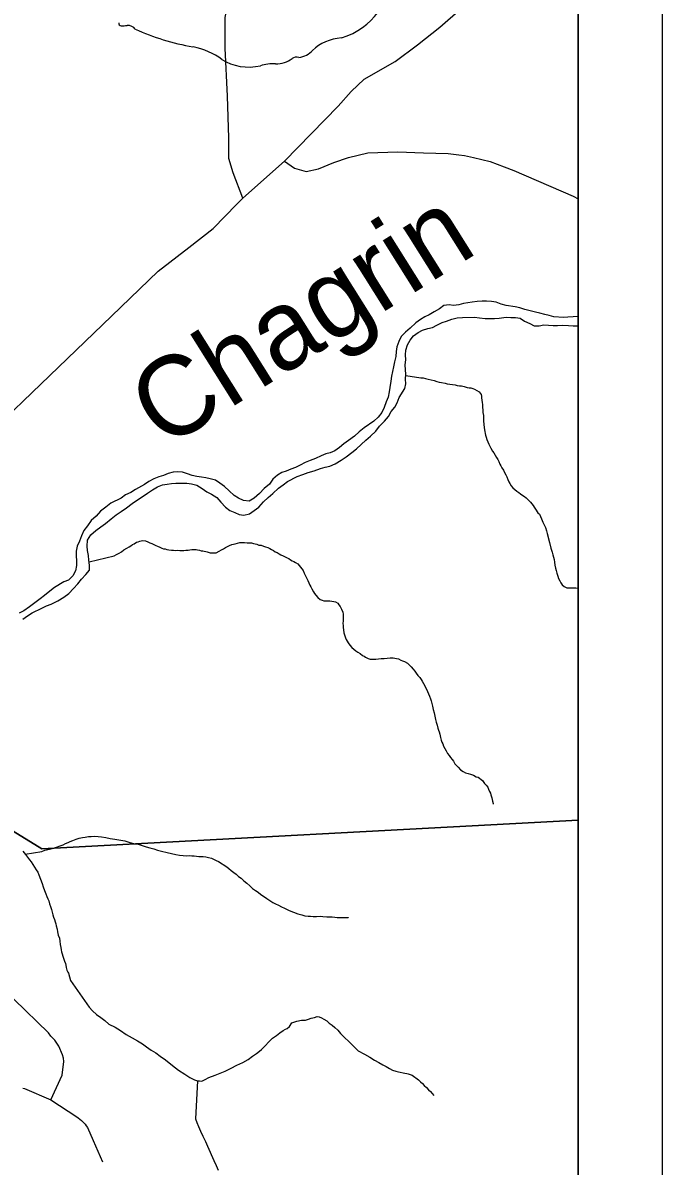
# Model space of a CAD drawing. Extents: x 0 to 44.3, y 0 to 22.
# Drawn here: x 8.24 to 9, y 17.041 to 18.401 of the extents above; entities that cross this region are included whole.
import ezdxf

# ---------------------------------------------------------------- set-up
doc = ezdxf.new("R2010")
doc.units = 0
for name, color, linetype in [('GM_X_City_Street', 7, 'Continuous'), ('GM_X_Corporation', 7, 'Continuous'), ('GM_X_County_Road', 7, 'Continuous'), ('GM_X_Minor_River', 7, 'Continuous'), ('GM_X_Minor_River_Text', 7, 'Continuous'), ('GM_X_State_Route', 7, 'Continuous'), ('GM_X_State_Shield', 7, 'Continuous'), ('SH_Data', 7, 'Continuous')]:
    doc.layers.add(name, color=color, linetype=linetype)

msp = doc.modelspace()

# ---------------------------------------------------------------- linework, layer by layer
at = {"layer": 'GM_X_City_Street'}
for points in [[(8.5507, 18.2363), (8.5628, 18.2282), (8.5765, 18.2242), (8.5913, 18.2273), (8.6095, 18.2347), (8.6269, 18.2407), (8.6499, 18.2464), (8.6858, 18.2473), (8.7162, 18.2461), (8.7454, 18.2454), (8.7581, 18.2438), (8.7651, 18.243), (8.7756, 18.2407), (8.7955, 18.2358), (8.8122, 18.2296), (8.8237, 18.2251), (8.8942, 18.1946), (8.9, 18.1917)], [(8.2727, 17.1196), (8.2864, 17.1487), (8.2884, 17.165), (8.2879, 17.1689), (8.2866, 17.1731), (8.2824, 17.1832), (8.2775, 17.1905), (8.2729, 17.1954), (8.27, 17.1993), (8.2291, 17.239), (8.1807, 17.2908)], [(8.2394, 17.1336), (8.2414, 17.133), (8.2727, 17.1196), (8.3037, 17.0991), (8.3054, 17.098), (8.3075, 17.0965), (8.3094, 17.0949), (8.3136, 17.0904), (8.3151, 17.0884), (8.3166, 17.0865), (8.3233, 17.0713), (8.3342, 17.0458)]]:
    msp.add_lwpolyline(points, dxfattribs=at)
at = {"layer": 'GM_X_Corporation'}
for points in [[(8.9, 14.1), (8.9, 20.9), (3.6041, 20.9)], [(8.9, 14.1), (8.9, 20.9), (3.6041, 20.9)], [(8.0905, 17.5236), (8.262, 17.4181), (8.9, 17.4522), (8.9, 19.3141)], [(8.9, 14.1), (8.9, 17.4522), (8.262, 17.4181), (8.0905, 17.5236)]]:
    msp.add_lwpolyline(points, dxfattribs=at)
at = {"layer": 'GM_X_County_Road'}
msp.add_lwpolyline([(8.5014, 18.1922), (8.5507, 18.2363), (8.6148, 18.3016), (8.6301, 18.3193), (8.6454, 18.3338), (8.6823, 18.3548), (8.7091, 18.3746), (8.7357, 18.3959), (8.7607, 18.4177), (8.9, 18.5298)], dxfattribs=at)
at = {"layer": 'GM_X_Minor_River'}
for points in [[(8.9, 18.0516), (8.8994, 18.0516), (8.8941, 18.0512), (8.888, 18.0508), (8.8827, 18.0504), (8.8713, 18.0512), (8.8656, 18.0527), (8.8603, 18.0538), (8.8546, 18.0553), (8.8493, 18.0568), (8.8429, 18.0583), (8.8368, 18.0598), (8.8307, 18.0617), (8.825, 18.0632), (8.8144, 18.0647), (8.8087, 18.0662), (8.8026, 18.0685), (8.7969, 18.0692), (8.7912, 18.0696), (8.7859, 18.0699), (8.7799, 18.0695), (8.7742, 18.0684), (8.7636, 18.0669), (8.7583, 18.0653), (8.7518, 18.0645), (8.7465, 18.0653), (8.7404, 18.0645), (8.7351, 18.0607), (8.7287, 18.0569), (8.723, 18.0535), (8.7177, 18.0512), (8.7124, 18.0481), (8.7071, 18.0439), (8.7003, 18.0378), (8.6946, 18.0329), (8.6897, 18.0276), (8.6867, 18.0219), (8.6844, 18.0154), (8.6837, 18.0097), (8.6833, 18.004), (8.6815, 17.9975), (8.6803, 17.9915), (8.6792, 17.9862), (8.6781, 17.9805), (8.6774, 17.9744), (8.6762, 17.9672), (8.6755, 17.9618), (8.674, 17.9554), (8.6717, 17.9501), (8.6695, 17.9432), (8.6665, 17.9375), (8.6623, 17.9318), (8.657, 17.9269), (8.6457, 17.9192), (8.6396, 17.9143), (8.6339, 17.9093), (8.6271, 17.904), (8.6214, 17.9002), (8.6161, 17.8956), (8.6105, 17.8918), (8.6052, 17.8895), (8.5999, 17.888), (8.5946, 17.8857), (8.5877, 17.8827), (8.5813, 17.88), (8.5756, 17.8777), (8.5696, 17.8746), (8.5639, 17.872), (8.5582, 17.8697), (8.5529, 17.8674), (8.5476, 17.8659), (8.5423, 17.8628), (8.537, 17.8579), (8.5328, 17.8521), (8.5268, 17.8468), (8.5211, 17.8411), (8.5147, 17.8354), (8.5086, 17.832), (8.5022, 17.8327), (8.4961, 17.8354), (8.4908, 17.8384), (8.4851, 17.8441), (8.4794, 17.8494)], [(8.6951, 17.9999), (8.6947, 18.0059), (8.6951, 18.0116), (8.6973, 18.0177), (8.7004, 18.0234), (8.7041, 18.0287), (8.7098, 18.0325), (8.7151, 18.0352), (8.7212, 18.0371), (8.7269, 18.0383), (8.7322, 18.0413), (8.7382, 18.0444), (8.7435, 18.0459), (8.75, 18.0482), (8.7564, 18.0501), (8.7625, 18.0505), (8.7769, 18.0506), (8.7826, 18.0498), (8.7894, 18.0491), (8.8008, 18.0491), (8.8061, 18.0495), (8.8144, 18.0506), (8.8201, 18.0503), (8.8254, 18.0503), (8.8311, 18.0495), (8.8364, 18.0461), (8.8425, 18.0431), (8.8478, 18.0405), (8.8539, 18.0405), (8.8592, 18.0416), (8.8649, 18.0413), (8.8702, 18.0409), (8.8755, 18.0409), (8.8816, 18.0413), (8.8888, 18.0409), (8.8941, 18.0406), (8.9, 18.0406)], [(8.2394, 17.6916), (8.245, 17.6954), (8.2507, 17.6988), (8.2621, 17.7046), (8.2678, 17.7072), (8.2731, 17.7091), (8.2814, 17.7133), (8.2882, 17.7175), (8.2943, 17.7221), (8.2999, 17.7278), (8.3049, 17.7335), (8.3094, 17.7392), (8.3147, 17.7445), (8.3188, 17.7499), (8.3188, 17.7556), (8.318, 17.7616), (8.3177, 17.7673), (8.3165, 17.773), (8.3161, 17.7783), (8.3165, 17.7856), (8.3206, 17.7916), (8.3263, 17.797), (8.3323, 17.8012), (8.338, 17.8054), (8.3445, 17.8107), (8.3505, 17.8156), (8.3566, 17.8195), (8.363, 17.824), (8.3698, 17.829), (8.3759, 17.8335), (8.3827, 17.8377), (8.388, 17.8415), (8.3937, 17.8454), (8.3997, 17.8488), (8.4058, 17.8511), (8.4111, 17.8522), (8.4164, 17.853), (8.4217, 17.8534), (8.4278, 17.8534), (8.4346, 17.8531), (8.4403, 17.8523), (8.4467, 17.8508), (8.4528, 17.847), (8.4585, 17.8429), (8.4638, 17.8402), (8.4703, 17.8361), (8.4752, 17.8307), (8.4806, 17.8247), (8.4859, 17.8209), (8.4916, 17.8183), (8.4969, 17.816), (8.5026, 17.8152), (8.509, 17.8168), (8.5147, 17.8206), (8.5204, 17.8248), (8.5257, 17.8309), (8.5314, 17.8362), (8.537, 17.8411), (8.5438, 17.8472), (8.5491, 17.8514), (8.5544, 17.8552), (8.5658, 17.861), (8.5726, 17.8636), (8.5791, 17.8659), (8.5863, 17.8678), (8.5938, 17.8705), (8.5991, 17.8724), (8.6048, 17.8736), (8.6109, 17.8763), (8.6181, 17.8804), (8.6241, 17.8846), (8.6309, 17.8896), (8.6366, 17.8942), (8.6419, 17.8991), (8.6476, 17.9044), (8.6533, 17.909), (8.6593, 17.9151), (8.6639, 17.9212), (8.6699, 17.9269), (8.6744, 17.9326), (8.6778, 17.9383), (8.682, 17.9436), (8.685, 17.949), (8.6873, 17.955), (8.6941, 17.9657), (8.6952, 17.9714), (8.6948, 17.9771), (8.6952, 17.9828), (8.6948, 17.9881), (8.6944, 17.9942), (8.6951, 17.9999)], [(8.6951, 17.9812), (8.7131, 17.9787), (8.7158, 17.9784), (8.7185, 17.9777), (8.7219, 17.977), (8.7254, 17.976), (8.7288, 17.9753), (8.7319, 17.9742), (8.7346, 17.9735), (8.7376, 17.9729), (8.7418, 17.9722), (8.7445, 17.9715), (8.7476, 17.9712), (8.7507, 17.9705), (8.7537, 17.9702), (8.7564, 17.9695), (8.7591, 17.9692), (8.7614, 17.9689), (8.7644, 17.9682), (8.7679, 17.9672), (8.7706, 17.9668), (8.7725, 17.9665), (8.7748, 17.9658), (8.7767, 17.9651), (8.7794, 17.9636), (8.7825, 17.9618), (8.7849, 17.9588), (8.7853, 17.9569), (8.7853, 17.9547), (8.7854, 17.952), (8.7859, 17.9493), (8.7863, 17.9467), (8.7864, 17.9436), (8.7869, 17.9402), (8.7869, 17.9372), (8.7874, 17.9338), (8.7875, 17.9303), (8.7876, 17.9273), (8.7881, 17.9231), (8.7882, 17.9193), (8.7886, 17.9167), (8.7899, 17.9102), (8.7907, 17.908), (8.7916, 17.9053), (8.7928, 17.9023), (8.794, 17.8997), (8.7952, 17.8974), (8.7964, 17.8948), (8.7984, 17.8914), (8.8, 17.8892), (8.8016, 17.8865), (8.8028, 17.8839), (8.8044, 17.8813), (8.8056, 17.879), (8.8068, 17.876), (8.808, 17.8737), (8.8092, 17.8715), (8.8115, 17.8685), (8.8124, 17.8659), (8.814, 17.8632), (8.8152, 17.8606), (8.8164, 17.8576), (8.8176, 17.855), (8.8188, 17.8527), (8.8204, 17.8501), (8.8224, 17.8478), (8.8247, 17.8456), (8.827, 17.8438), (8.8294, 17.8423), (8.8317, 17.8405), (8.8344, 17.8386), (8.8363, 17.8372), (8.8383, 17.8357), (8.8402, 17.8338), (8.8434, 17.8305), (8.8449, 17.8286), (8.8465, 17.8267), (8.8477, 17.8245), (8.8493, 17.8223), (8.8521, 17.8181), (8.854, 17.8163), (8.8552, 17.8136), (8.8565, 17.8106), (8.8581, 17.8069), (8.8597, 17.8035), (8.8613, 17.8005), (8.8625, 17.7967), (8.8634, 17.7933), (8.8659, 17.7827), (8.8676, 17.7759), (8.8693, 17.771), (8.8701, 17.7679), (8.8709, 17.7653), (8.8714, 17.7623), (8.8719, 17.7592), (8.8723, 17.7558), (8.8732, 17.752), (8.874, 17.7494)], [(8.4794, 17.8494), (8.474, 17.8531), (8.4687, 17.8566), (8.4626, 17.8584), (8.4573, 17.8596), (8.452, 17.8603), (8.4467, 17.8611), (8.441, 17.8622), (8.4353, 17.8644), (8.4296, 17.8663), (8.4239, 17.8667), (8.4183, 17.8663), (8.4126, 17.8648), (8.4069, 17.8625), (8.4012, 17.8606), (8.3955, 17.8583), (8.3895, 17.8552), (8.3842, 17.8518), (8.3736, 17.8457), (8.3679, 17.8423), (8.3618, 17.8392), (8.3565, 17.8354), (8.3444, 17.8293), (8.3384, 17.8247), (8.3319, 17.8198), (8.327, 17.8141), (8.321, 17.8087), (8.3164, 17.8023), (8.3123, 17.7969), (8.3092, 17.7905), (8.307, 17.7844), (8.3043, 17.7783), (8.3029, 17.7722), (8.3029, 17.7669), (8.3036, 17.7608), (8.3033, 17.7552), (8.3022, 17.7491), (8.2991, 17.743), (8.2938, 17.738), (8.2885, 17.7358), (8.2772, 17.7289), (8.2715, 17.7247), (8.2655, 17.7194), (8.2602, 17.7156), (8.2537, 17.711), (8.2477, 17.706), (8.2409, 17.7015), (8.2352, 17.6984)], [(8.3183, 17.7596), (8.3483, 17.7669), (8.3509, 17.7684), (8.3543, 17.7701), (8.3569, 17.7716), (8.3599, 17.774), (8.3633, 17.776), (8.3659, 17.7776), (8.3681, 17.7788), (8.37, 17.7804), (8.3719, 17.7812), (8.3749, 17.7831), (8.3768, 17.7836), (8.3787, 17.7844), (8.3821, 17.7852), (8.3855, 17.7846), (8.3882, 17.7835), (8.3905, 17.7824), (8.3932, 17.7813), (8.3955, 17.7802), (8.3978, 17.7792), (8.3998, 17.7781), (8.4025, 17.777), (8.4048, 17.7759), (8.4067, 17.7752), (8.409, 17.7749), (8.4109, 17.7742), (8.4132, 17.7738), (8.4163, 17.7735), (8.4186, 17.7736), (8.4212, 17.7733), (8.4239, 17.7734), (8.4262, 17.773), (8.4289, 17.7731), (8.4311, 17.7732), (8.4334, 17.7736), (8.4361, 17.7737), (8.4384, 17.7741), (8.4406, 17.7742), (8.4433, 17.7742), (8.4456, 17.7743), (8.4475, 17.774), (8.4498, 17.7736), (8.4517, 17.7729), (8.4536, 17.7726), (8.459, 17.7716), (8.4624, 17.7705), (8.4644, 17.7702), (8.4666, 17.7703), (8.4697, 17.7703), (8.4731, 17.7723), (8.4757, 17.7739), (8.4783, 17.7751), (8.4806, 17.7767), (8.4832, 17.7779), (8.4855, 17.7791), (8.4881, 17.7803), (8.4923, 17.7812), (8.4949, 17.782), (8.4976, 17.7825), (8.5006, 17.7825), (8.5033, 17.7826), (8.5063, 17.7823), (8.509, 17.7824), (8.5117, 17.7821), (8.514, 17.7814), (8.5159, 17.781), (8.5178, 17.7807), (8.5201, 17.7796), (8.5232, 17.7793), (8.5259, 17.7782), (8.5282, 17.7775), (8.5309, 17.7765), (8.5332, 17.7754), (8.5355, 17.7743), (8.5378, 17.7732), (8.5397, 17.7717), (8.5421, 17.7706), (8.5444, 17.7692), (8.5463, 17.7681), (8.5494, 17.7666), (8.5517, 17.7656), (8.554, 17.7645), (8.556, 17.7634), (8.5579, 17.7619), (8.5598, 17.7608), (8.5618, 17.7601), (8.5641, 17.759), (8.5668, 17.7572), (8.5731, 17.7494), (8.5743, 17.7463), (8.5759, 17.7429), (8.5775, 17.7399), (8.5787, 17.7373), (8.5799, 17.7347), (8.5811, 17.732), (8.5823, 17.7298), (8.5835, 17.7275)], [(8.874, 17.7494), (8.8749, 17.746), (8.8761, 17.7426), (8.8769, 17.7399), (8.8782, 17.7369), (8.8794, 17.7347), (8.8809, 17.7321), (8.8833, 17.7302), (8.8867, 17.7288), (8.8894, 17.7285), (8.8928, 17.7285), (8.8955, 17.7286), (8.8974, 17.7287), (8.8997, 17.7283), (8.9, 17.7283)], [(8.5835, 17.7275), (8.5852, 17.7241), (8.5864, 17.7219), (8.5879, 17.72), (8.5903, 17.717), (8.5934, 17.7148), (8.5957, 17.7141), (8.5976, 17.7134), (8.5999, 17.7131), (8.6018, 17.7131), (8.6049, 17.7132), (8.6072, 17.7129), (8.6094, 17.7126), (8.6114, 17.7119), (8.6141, 17.7104), (8.6156, 17.7086), (8.6172, 17.7063), (8.6188, 17.7033), (8.6201, 17.6999), (8.6205, 17.6973), (8.6206, 17.6953), (8.6206, 17.6931), (8.6207, 17.6893), (8.6204, 17.6862), (8.6205, 17.6839), (8.6205, 17.6816), (8.621, 17.6786), (8.6215, 17.6752), (8.6235, 17.6692), (8.6243, 17.6673), (8.6267, 17.6631), (8.6287, 17.6605), (8.631, 17.6579), (8.6334, 17.6557), (8.6357, 17.6538), (8.638, 17.652), (8.6408, 17.6506), (8.6435, 17.6483), (8.6454, 17.6472), (8.6473, 17.6461), (8.6504, 17.6447), (8.6527, 17.644), (8.6554, 17.6437), (8.6573, 17.6437), (8.6596, 17.6438), (8.6626, 17.6443), (8.6657, 17.6447), (8.6695, 17.6448), (8.6729, 17.6449), (8.6767, 17.6454), (8.6801, 17.6455), (8.682, 17.6451), (8.6839, 17.6448), (8.6866, 17.6441), (8.6893, 17.6426), (8.6913, 17.6419), (8.6936, 17.6409), (8.697, 17.639), (8.6998, 17.6364), (8.7013, 17.6346), (8.7037, 17.632), (8.7057, 17.6297), (8.7076, 17.6271), (8.7096, 17.6245), (8.7116, 17.6219), (8.7132, 17.6196), (8.7144, 17.6178), (8.7163, 17.6148), (8.7196, 17.608), (8.7208, 17.6054), (8.722, 17.6024), (8.7232, 17.5997), (8.7244, 17.5967), (8.7252, 17.5941), (8.7261, 17.591), (8.7269, 17.588), (8.7278, 17.5838), (8.7287, 17.5801), (8.7295, 17.5759), (8.7304, 17.5721), (8.7312, 17.5687), (8.7325, 17.5653), (8.7333, 17.5619), (8.7341, 17.5593), (8.7349, 17.5574), (8.7354, 17.5547), (8.7358, 17.5528), (8.7363, 17.5506), (8.7371, 17.5475), (8.7379, 17.5449), (8.7391, 17.543), (8.74, 17.5404), (8.7416, 17.5374), (8.7431, 17.5347), (8.7447, 17.5317), (8.7467, 17.5291), (8.7483, 17.5269), (8.7503, 17.5243), (8.7518, 17.5224), (8.7534, 17.5194), (8.7554, 17.5175)], [(8.7554, 17.5175), (8.7574, 17.5153), (8.7601, 17.5123), (8.7632, 17.5101), (8.7663, 17.5087), (8.7694, 17.5076), (8.772, 17.5069), (8.7755, 17.5059), (8.779, 17.504), (8.7813, 17.5033), (8.7863, 17.4993), (8.7887, 17.4959), (8.7907, 17.4941), (8.7926, 17.4914), (8.7935, 17.4892), (8.7947, 17.4865), (8.7959, 17.4843), (8.7963, 17.4824), (8.7975, 17.479), (8.798, 17.4767), (8.7984, 17.4748), (8.7992, 17.4722), (8.7992, 17.4718), (8.7996, 17.4714)], [(8.2423, 17.412), (8.262, 17.4151), (8.2658, 17.4164), (8.2711, 17.4176), (8.276, 17.4189), (8.2874, 17.423), (8.2904, 17.4246), (8.2934, 17.4258), (8.296, 17.427), (8.299, 17.4282), (8.3032, 17.4295), (8.3066, 17.4307), (8.3104, 17.4316), (8.3138, 17.432), (8.3176, 17.4329), (8.321, 17.433), (8.3248, 17.4331), (8.329, 17.4328), (8.3332, 17.4325), (8.3382, 17.4315), (8.3435, 17.4305), (8.3489, 17.4295), (8.3562, 17.4286), (8.3608, 17.4275), (8.3657, 17.4261), (8.3711, 17.4247), (8.3769, 17.4237), (8.3815, 17.4223), (8.3861, 17.4206), (8.3907, 17.4195), (8.3953, 17.4181), (8.3999, 17.4167), (8.4045, 17.4153), (8.4114, 17.4136), (8.4164, 17.4126), (8.4214, 17.4116), (8.426, 17.4105), (8.4301, 17.4103), (8.4343, 17.41), (8.4374, 17.4101), (8.4404, 17.4098), (8.4435, 17.4098), (8.4462, 17.4095), (8.4488, 17.4092), (8.4511, 17.4089), (8.4542, 17.409), (8.4572, 17.4087), (8.4603, 17.408), (8.4641, 17.4069), (8.4664, 17.4058), (8.4695, 17.4044), (8.4722, 17.4029), (8.4823, 17.3967), (8.4846, 17.3949), (8.4874, 17.3923), (8.4905, 17.3901), (8.4932, 17.3879), (8.4963, 17.3853), (8.4994, 17.3831), (8.5025, 17.3801), (8.506, 17.3772), (8.5095, 17.3742), (8.5127, 17.3709), (8.5165, 17.3687), (8.5196, 17.3665), (8.5228, 17.3639), (8.5259, 17.3617), (8.5297, 17.3591), (8.5332, 17.3565), (8.5371, 17.3543), (8.5402, 17.3529), (8.5437, 17.3511), (8.5471, 17.3493), (8.551, 17.3475), (8.5564, 17.3449), (8.5614, 17.3428), (8.5668, 17.341), (8.5714, 17.3396), (8.5752, 17.3386), (8.579, 17.3379), (8.5817, 17.338), (8.5851, 17.3377), (8.589, 17.3378), (8.5931, 17.3379), (8.5966, 17.3376), (8.6012, 17.3373), (8.6046, 17.3374), (8.6076, 17.3371), (8.6107, 17.3368), (8.6134, 17.3365), (8.616, 17.3365), (8.6179, 17.3366), (8.6202, 17.3363), (8.6225, 17.3363), (8.6248, 17.3364), (8.6267, 17.3364), (8.6267, 17.3361), (8.6267, 17.3364)], [(8.2395, 17.4153), (8.2411, 17.4134), (8.2427, 17.4116), (8.2439, 17.4097), (8.2474, 17.4052), (8.2494, 17.4026)], [(8.2494, 17.4026), (8.2514, 17.3996), (8.2534, 17.3962), (8.2554, 17.3932), (8.2573, 17.3902), (8.2586, 17.3872), (8.2626, 17.3771), (8.2639, 17.3729), (8.2655, 17.3684), (8.2668, 17.3646), (8.268, 17.3616), (8.2692, 17.3586), (8.2704, 17.3563), (8.2712, 17.3529), (8.2725, 17.3495), (8.2737, 17.3461), (8.2745, 17.3427), (8.2754, 17.3397), (8.2762, 17.3367), (8.2771, 17.334), (8.2779, 17.3314), (8.2787, 17.3291), (8.2792, 17.3264), (8.2804, 17.3227), (8.2809, 17.3193), (8.2817, 17.3155), (8.283, 17.3117), (8.2834, 17.3083), (8.2839, 17.3045), (8.2848, 17.3007), (8.2852, 17.298), (8.2857, 17.2958), (8.2865, 17.2931), (8.2873, 17.2905), (8.2878, 17.2882), (8.289, 17.2844), (8.2902, 17.2818), (8.2906, 17.2799), (8.2911, 17.2769), (8.2919, 17.2738), (8.2931, 17.2716), (8.2939, 17.2701), (8.2964, 17.2616)], [(8.2964, 17.2616), (8.3184, 17.2298), (8.3226, 17.2253), (8.3273, 17.2212), (8.3323, 17.2175), (8.3373, 17.2141), (8.3419, 17.2097), (8.3496, 17.206), (8.3557, 17.2019), (8.3626, 17.1974), (8.3695, 17.1933), (8.376, 17.1896), (8.3818, 17.1863), (8.3868, 17.1826), (8.3922, 17.1788), (8.3976, 17.1755), (8.4029, 17.1714), (8.4091, 17.1673), (8.4176, 17.1602), (8.4249, 17.155), (8.4322, 17.1501), (8.4383, 17.1461), (8.4437, 17.1435), (8.4475, 17.142), (8.4498, 17.142), (8.4524, 17.1417), (8.4566, 17.1437), (8.4607, 17.146), (8.4683, 17.1488), (8.4743, 17.1511), (8.4804, 17.1535), (8.4872, 17.157), (8.4943, 17.1606), (8.5011, 17.1641), (8.5075, 17.1676), (8.5128, 17.1715), (8.5176, 17.1746), (8.521, 17.1773), (8.5236, 17.1796), (8.5367, 17.1928), (8.5412, 17.1959), (8.5454, 17.1993), (8.5491, 17.2021), (8.5521, 17.2036), (8.554, 17.2044), (8.5566, 17.2067), (8.5596, 17.211), (8.5653, 17.2133), (8.5709, 17.2142), (8.5759, 17.2142), (8.5793, 17.2154), (8.5827, 17.2166), (8.5846, 17.217), (8.5865, 17.2174), (8.5895, 17.2186), (8.5922, 17.2183), (8.5948, 17.2172), (8.5975, 17.2153), (8.601, 17.2135), (8.6041, 17.2109), (8.6075, 17.2082), (8.6106, 17.2056), (8.6141, 17.2026), (8.6176, 17.1985), (8.6222, 17.1936), (8.6272, 17.1888), (8.6326, 17.1839), (8.6384, 17.1779), (8.6461, 17.1738), (8.6522, 17.1701), (8.658, 17.1668), (8.663, 17.1638), (8.6676, 17.1612), (8.6718, 17.159), (8.6756, 17.1568), (8.6794, 17.1549), (8.6833, 17.1535), (8.6863, 17.1528), (8.6886, 17.1524), (8.692, 17.1517), (8.6939, 17.1513), (8.6962, 17.151), (8.6981, 17.1503), (8.7004, 17.1495), (8.7027, 17.1488), (8.7104, 17.1432), (8.7127, 17.141), (8.715, 17.1391), (8.717, 17.1365), (8.7197, 17.1342), (8.722, 17.1316), (8.7243, 17.1294), (8.7263, 17.1271), (8.7285, 17.1246)], [(8.4475, 17.142), (8.4448, 17.0971), (8.4464, 17.0926), (8.4484, 17.0876), (8.4508, 17.0824), (8.4535, 17.0763), (8.4567, 17.0699), (8.4594, 17.0642), (8.4669, 17.0472), (8.4697, 17.0412), (8.472, 17.0359)]]:
    msp.add_lwpolyline(points, dxfattribs=at)
at = {"layer": 'GM_X_State_Route'}
msp.add_line((8.4943, 18.185), (8.5014, 18.1922), dxfattribs=at)
for points in [[(8.5014, 18.1922), (8.4898, 18.2223), (8.4848, 18.2394), (8.4846, 18.2641), (8.4829, 18.3135), (8.4804, 18.3709), (8.4804, 18.4073), (8.4858, 18.436), (8.5325, 18.5651), (8.5415, 18.5965), (8.5432, 18.6144), (8.5429, 18.6258)], [(8.3449, 18.0519), (8.4005, 18.1054), (8.4371, 18.1337), (8.4661, 18.1561), (8.4943, 18.185)], [(8.0818, 17.8054), (8.0998, 17.8165), (8.1239, 17.8393), (8.3449, 18.0519)]]:
    msp.add_lwpolyline(points, dxfattribs=at)
at = {"layer": 'GM_X_State_Shield'}
for centre, major_axis, start_param, end_param in [((8.5855, 18.4476), (0.0874, 0), 5.101752, 6.440018), ((8.3575, 18.4005), (0.00385, 0), 3.00124, 4.508301), ((8.3581, 18.4209), (0.0294, 0), 4.665946, 4.897461), ((8.3641, 18.3893), (0.0106, 0), 0.519207, 1.627899), ((8.4979, 18.5691), (0.2524, 0), 4.195997, 4.488961), ((8.6223, 18.3447), (0.0479, 0), 1.647645, 2.488434), ((8.4227, 18.311), (0.079, 0), 0.823519, 1.323587), ((8.5617, 18.3815), (0.0282, 0), 4.937069, 5.64225), ((8.5081, 18.3884), (0.0501, 0), 4.026481, 4.996735), ((8.5371, 18.3192), (0.0412, 0), 1.495662, 1.94098), ((8.5407, 18.3734), (0.0267, 0), 4.691044, 5.507374), ((8.5649, 18.354), (0.00752, 0), 1.147584, 2.315152)]:
    msp.add_ellipse(centre, major_axis=major_axis, ratio=0.8, start_param=start_param, end_param=end_param, dxfattribs=at)
at = {"layer": 'SH_Data'}
for p, q in [((9, 21), (9, 14)), ((8.9, 20.9), (8.9, 14.1)), ((8.9, 20.9), (8.9, 14.1))]:
    msp.add_line(p, q, dxfattribs=at)

# ---------------------------------------------------------------- texts
at = {"layer": 'GM_X_Minor_River_Text'}
msp.add_text('Chagrin', height=0.09476, rotation=32.1193, dxfattribs=at).set_placement((8.4069, 17.8924))

doc.saveas('drawing.dxf')
